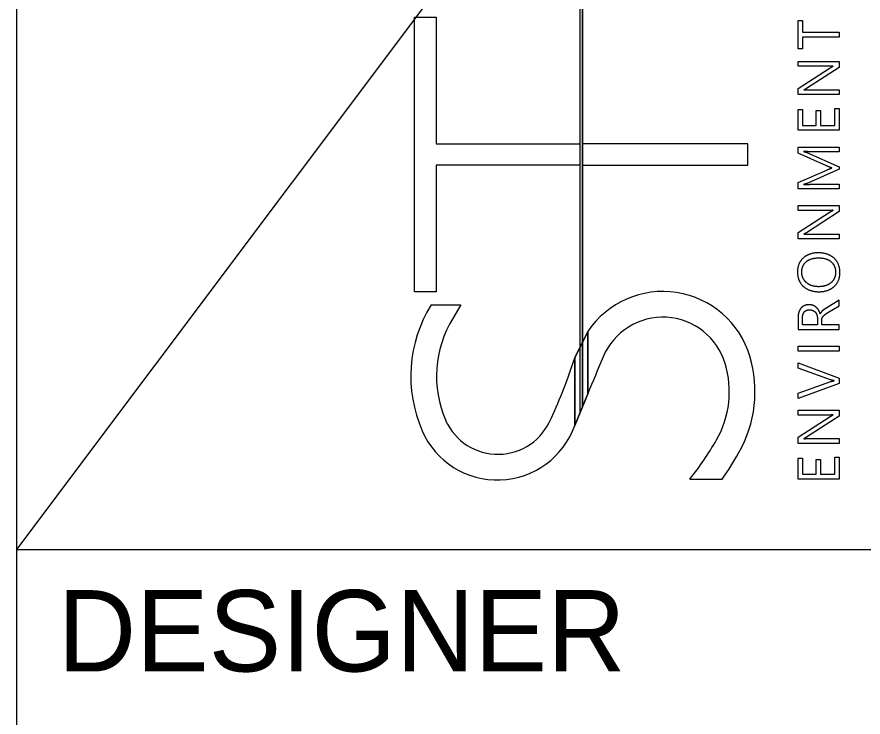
# Model space of a CAD drawing. Extents: x 0 to 104, y 0 to 37.
# Drawn here: x 32 to 33.04, y 2.794 to 3.654 of the extents above; entities that cross this region are included whole.
import ezdxf

# ---------------------------------------------------------------- set-up
doc = ezdxf.new("R2010")
doc.units = 0
for name, color, linetype in [('SH_Border', 7, 'Continuous'), ('SH_Cut_Line', 7, 'Continuous'), ('SH_Named_Boundary', 7, 'Continuous')]:
    doc.layers.add(name, color=color, linetype=linetype)

msp = doc.modelspace()

# ---------------------------------------------------------------- linework, layer by layer
at = {"layer": 'SH_Border'}
msp.add_line((32, 3), (33.5, 5), dxfattribs=at)
at = {"layer": 'SH_Cut_Line'}
for p, q in [((32.6923, 3.7993), (32.6923, 3.168)), ((32.6954, 3.7993), (32.6954, 3.1758)), ((32.489, 3.3165), (32.489, 3.6543)), ((32.489, 3.6543), (32.5153, 3.6543)), ((32.5153, 3.6543), (32.5153, 3.4985)), ((33.0035, 3.594), (33.0035, 3.5941)), ((32.9676, 3.5648), (32.9676, 3.5646)), ((32.5153, 3.4985), (32.6923, 3.4985)), ((32.6923, 3.4985), (32.6923, 3.4722)), ((32.8988, 3.4985), (32.6954, 3.4985)), ((32.6954, 3.4985), (32.6954, 3.4722)), ((32.8988, 3.4722), (32.8988, 3.4985)), ((32.9673, 3.4892), (32.9673, 3.489)), ((32.6923, 3.4722), (32.5153, 3.4722)), ((32.5153, 3.4722), (32.5153, 3.3165)), ((32.6954, 3.4722), (32.8988, 3.4722)), ((33.0018, 3.4687), (33.0018, 3.4689)), ((32.9673, 3.4486), (32.9673, 3.4484)), ((33.0035, 3.4168), (33.0035, 3.4169)), ((32.9676, 3.3876), (32.9676, 3.3874)), ((32.965, 3.3408), (32.965, 3.3408)), ((33.0119, 3.3404), (33.0119, 3.3404)), ((32.5153, 3.3165), (32.489, 3.3165)), ((32.5092, 3.3005), (32.5459, 3.3005)), ((32.5459, 3.3005), (32.5361, 3.2839)), ((32.9877, 3.2895), (32.9876, 3.2895)), ((32.7018, 3.2679), (32.7018, 3.1912)), ((32.686, 3.2356), (32.686, 3.1524)), ((33.005, 3.2072), (33.005, 3.2074)), ((33.0035, 3.1654), (33.0035, 3.1655)), ((32.9676, 3.1362), (32.9676, 3.136)), ((32.8274, 3.0863), (32.867, 3.0863))]:
    msp.add_line(p, q, dxfattribs=at)
for points in [[(32.6149, 3.8575), (32.6891, 3.8391), (32.6891, 3.7993), (32.6923, 3.7993), (32.6923, 3.168)], [(32.6954, 3.1758), (32.6954, 3.7993), (32.6986, 3.7993), (32.6986, 3.8368), (32.8317, 3.8038)], [(32.9961, 3.5938), (32.9605, 3.5938), (32.9605, 3.5997), (33.011, 3.5997), (33.011, 3.5924), (32.9708, 3.5664)], [(32.9745, 3.5649), (33.011, 3.5649), (33.011, 3.559), (32.9605, 3.559), (32.9605, 3.5666), (33.0001, 3.5919)], [(32.9956, 3.4713), (32.9605, 3.4871), (32.9605, 3.4945), (33.011, 3.4945), (33.011, 3.4887), (32.9771, 3.4887)], [(32.9722, 3.4875), (33.011, 3.4702), (33.011, 3.4673), (32.9725, 3.4501)], [(32.9772, 3.4487), (33.011, 3.4487), (33.011, 3.443), (32.9605, 3.443), (32.9605, 3.4508), (32.9957, 3.4663)], [(32.9961, 3.4165), (32.9605, 3.4165), (32.9605, 3.4225), (33.011, 3.4225), (33.011, 3.4152), (32.9708, 3.3892)], [(32.9745, 3.3876), (33.011, 3.3876), (33.011, 3.3817), (32.9605, 3.3817), (32.9605, 3.3894), (33.0001, 3.4147)], [(32.5092, 3.3005), (32.5459, 3.3005), (32.5361, 3.2839)], [(32.9969, 3.291), (33.011, 3.2994), (33.011, 3.3065), (32.9958, 3.297)], [(32.9605, 3.2853), (32.9605, 3.2702), (33.011, 3.2702), (33.011, 3.2762), (32.9895, 3.2762), (32.9895, 3.281)], [(32.9842, 3.2842), (32.9842, 3.2762), (32.9659, 3.2762), (32.9659, 3.2843)], [(32.686, 3.1524), (32.686, 3.2356), (32.7018, 3.2679), (32.7018, 3.1912), (32.686, 3.1524)], [(32.7018, 3.2679), (32.7018, 3.1912)], [(32.686, 3.2356), (32.686, 3.1524)], [(33.0005, 3.2085), (32.9605, 3.2228), (32.9605, 3.2292), (33.011, 3.2105), (33.011, 3.204), (32.9605, 3.1856), (32.9605, 3.1922), (33.0006, 3.2062)], [(32.9961, 3.1651), (32.9605, 3.1651), (32.9605, 3.1711), (33.011, 3.1711), (33.011, 3.1638), (32.9708, 3.1378)], [(32.9745, 3.1362), (33.011, 3.1362), (33.011, 3.1303), (32.9605, 3.1303), (32.9605, 3.138), (33.0001, 3.1633)], [(32.8274, 3.0863), (32.867, 3.0863)]]:
    msp.add_lwpolyline(points, dxfattribs=at)
for points in [[(32.5153, 3.6543), (32.5153, 3.4985), (32.6923, 3.4985), (32.6923, 3.4722), (32.5153, 3.4722), (32.5153, 3.3165), (32.489, 3.3165), (32.489, 3.6543)], [(32.9659, 3.6501), (32.9659, 3.6355), (33.011, 3.6355), (33.011, 3.6296), (32.9659, 3.6296), (32.9659, 3.6151), (32.9605, 3.6151), (32.9605, 3.6501)], [(33.011, 3.5419), (33.011, 3.5151), (32.9605, 3.5151), (32.9605, 3.5408), (32.9659, 3.5408), (32.9659, 3.5211), (32.9827, 3.5211), (32.9827, 3.5393), (32.988, 3.5393), (32.988, 3.5211), (33.0057, 3.5211), (33.0057, 3.5419)], [(32.8988, 3.4722), (32.8988, 3.4985), (32.6954, 3.4985), (32.6954, 3.4722)], [(32.686, 3.2356), (32.686, 3.1524), (32.7018, 3.1912), (32.7018, 3.2679)], [(33.011, 3.2497), (33.011, 3.2437), (32.9605, 3.2437), (32.9605, 3.2497)], [(33.011, 3.1133), (33.011, 3.0865), (32.9605, 3.0865), (32.9605, 3.1122), (32.9659, 3.1122), (32.9659, 3.0924), (32.9827, 3.0924), (32.9827, 3.1107), (32.988, 3.1107), (32.988, 3.0924), (33.0057, 3.0924), (33.0057, 3.1133)]]:
    msp.add_lwpolyline(points, close=True, dxfattribs=at)
for centre, radius, start, end in [((32.7943, 3.2055), 0.1115, 16.5745, 146.0238), ((32.7943, 3.2055), 0.1115, 16.5745, 146.0238), ((32.6514, 3.2127), 0.1671, 148.3019, 203.5607), ((32.6514, 3.2127), 0.1671, 148.3019, 203.5607), ((32.6514, 3.2127), 0.1355, 148.3019, 203.5607), ((32.6514, 3.2127), 0.1355, 148.3019, 203.5607), ((32.7943, 3.2055), 0.0799, 16.5745, 157.0643), ((32.7943, 3.2055), 0.0799, 16.5745, 157.0643), ((32.0832, 3.4289), 0.633, 334.9549, 342.2202), ((32.0832, 3.4289), 0.633, 334.9549, 342.2202), ((40.2031, 0.1016), 8.1126, 157.26686, 157.61476), ((40.2031, 0.1016), 8.1126, 157.26686, 157.61476), ((32.7555, 3.194), 0.152, 330.4358, 16.5745), ((32.7555, 3.194), 0.152, 330.4358, 16.5745), ((32.7555, 3.194), 0.1204, 330.4358, 16.5745), ((32.7555, 3.194), 0.1204, 330.4358, 16.5745), ((40.2031, 0.1016), 8.1126, 157.73234, 157.79136), ((40.2031, 0.1016), 8.1126, 157.73234, 157.79136), ((32.5908, 3.1863), 0.101, 203.5866, 340.393), ((32.5908, 3.1863), 0.101, 203.5866, 340.393), ((32.5914, 3.1873), 0.0704, 204.1173, 338.0239), ((32.5914, 3.1873), 0.0704, 204.1173, 338.0239), ((32.5444, 3.3137), 0.363, 321.2094, 330.4358), ((32.5444, 3.3137), 0.363, 321.2094, 330.4358), ((32.5444, 3.3137), 0.3947, 324.8109, 330.4358), ((32.5444, 3.3137), 0.3947, 324.8109, 330.4358)]:
    msp.add_arc(centre, radius, start, end, dxfattribs=at)
for points in [[(33.0035, 3.5941), (33.0013, 3.5938), (32.9961, 3.5938)], [(33.0001, 3.5919), (33.0026, 3.5935), (33.0035, 3.594)], [(32.9708, 3.5664), (32.9692, 3.5654), (32.9676, 3.5648)], [(32.9676, 3.5646), (32.9692, 3.5649), (32.9745, 3.5649)], [(32.9771, 3.4887), (32.9731, 3.4887), (32.9673, 3.4892)], [(32.9673, 3.489), (32.9707, 3.4882), (32.9722, 3.4875)], [(33.0018, 3.4689), (32.9976, 3.4704), (32.9956, 3.4713)], [(32.9957, 3.4663), (32.9998, 3.4681), (33.0018, 3.4687)], [(32.9725, 3.4501), (32.9708, 3.4494), (32.9673, 3.4486)], [(32.9673, 3.4484), (32.9703, 3.4487), (32.9772, 3.4487)], [(33.0035, 3.4169), (33.0013, 3.4165), (32.9961, 3.4165)], [(33.0001, 3.4147), (33.0026, 3.4163), (33.0035, 3.4168)], [(32.9708, 3.3892), (32.9692, 3.3882), (32.9676, 3.3876)], [(32.9676, 3.3874), (32.9692, 3.3876), (32.9745, 3.3876)], [(32.9851, 3.3645), (32.9738, 3.3645), (32.9667, 3.3581)], [(33.0047, 3.3579), (32.9975, 3.3645), (32.9851, 3.3645)], [(32.9667, 3.3581), (32.9597, 3.3517), (32.9597, 3.3412)], [(32.965, 3.3408), (32.965, 3.349), (32.9705, 3.3536)], [(32.9705, 3.3536), (32.9759, 3.3583), (32.9859, 3.3583)], [(32.9859, 3.3583), (32.9957, 3.3583), (33.0011, 3.3535)], [(33.0011, 3.3535), (33.0066, 3.3487), (33.0066, 3.3404)], [(33.0119, 3.3404), (33.0119, 3.3514), (33.0047, 3.3579)], [(32.9597, 3.3412), (32.9597, 3.3299), (32.9669, 3.3233)], [(32.9708, 3.3279), (32.965, 3.3328), (32.965, 3.3408)], [(33.0066, 3.3404), (33.0066, 3.3326), (33.0009, 3.3277)], [(33.0048, 3.3232), (33.0119, 3.3296), (33.0119, 3.3404)], [(32.9669, 3.3233), (32.9742, 3.3167), (32.9864, 3.3167)], [(32.9858, 3.3229), (32.9765, 3.3229), (32.9708, 3.3279)], [(33.0009, 3.3277), (32.9952, 3.3229), (32.9858, 3.3229)], [(32.9864, 3.3167), (32.9977, 3.3167), (33.0048, 3.3232)], [(32.9681, 3.2995), (32.9655, 3.2984), (32.9638, 3.2963)], [(32.974, 3.3007), (32.9706, 3.3007), (32.9681, 3.2995)], [(32.9788, 3.2999), (32.9766, 3.3007), (32.974, 3.3007)], [(32.9827, 3.2976), (32.981, 3.2991), (32.9788, 3.2999)], [(32.9613, 3.2914), (32.9605, 3.2886), (32.9605, 3.2853)], [(32.9638, 3.2963), (32.9622, 3.2942), (32.9613, 3.2914)], [(32.9659, 3.2843), (32.9659, 3.2892), (32.9681, 3.2919)], [(32.9681, 3.2919), (32.9704, 3.2945), (32.9745, 3.2945)], [(32.9745, 3.2945), (32.9767, 3.2945), (32.9785, 3.2937)], [(32.9785, 3.2937), (32.9803, 3.2929), (32.9816, 3.2916)], [(32.9816, 3.2916), (32.9828, 3.2902), (32.9835, 3.2883)], [(32.9857, 3.2941), (32.9845, 3.2962), (32.9827, 3.2976)], [(32.9835, 3.2883), (32.9842, 3.2864), (32.9842, 3.2842)], [(32.9876, 3.2895), (32.9869, 3.2921), (32.9857, 3.2941)], [(32.989, 3.2917), (32.9883, 3.2908), (32.9877, 3.2895)], [(32.9907, 3.2935), (32.9897, 3.2926), (32.989, 3.2917)], [(32.9929, 3.2951), (32.9917, 3.2943), (32.9907, 3.2935)], [(32.9912, 3.2865), (32.9921, 3.2876), (32.9935, 3.2887)], [(32.9958, 3.297), (32.9942, 3.296), (32.9929, 3.2951)], [(32.9935, 3.2887), (32.9949, 3.2898), (32.9969, 3.291)], [(32.9895, 3.281), (32.9895, 3.2827), (32.9899, 3.284)], [(32.9899, 3.284), (32.9904, 3.2853), (32.9912, 3.2865)], [(33.005, 3.2074), (33.0029, 3.2077), (33.0005, 3.2085)], [(33.0006, 3.2062), (33.0025, 3.2069), (33.005, 3.2072)], [(33.0035, 3.1655), (33.0013, 3.1651), (32.9961, 3.1651)], [(33.0001, 3.1633), (33.0026, 3.1649), (33.0035, 3.1654)], [(32.9708, 3.1378), (32.9692, 3.1368), (32.9676, 3.1362)], [(32.9676, 3.136), (32.9692, 3.1362), (32.9745, 3.1362)]]:
    msp.add_open_spline(points, degree=2, dxfattribs=at)
at = {"layer": 'SH_Named_Boundary'}
for p, q in [((32, 0.5), (32, 21.5)), ((32, 3), (33.5, 3))]:
    msp.add_line(p, q, dxfattribs=at)

# ---------------------------------------------------------------- texts
at = {"layer": 'SH_Cut_Line'}
msp.add_text('DESIGNER', height=0.1, dxfattribs=at).set_placement((32.05, 2.85))

doc.saveas('drawing.dxf')
